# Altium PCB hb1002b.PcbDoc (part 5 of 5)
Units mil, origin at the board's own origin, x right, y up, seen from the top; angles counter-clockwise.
Board outline 2756 x 3549 mil, 2 copper layers (Top Layer, Bottom Layer); 120 components, 136 nets, 498 pads, 328 vias.
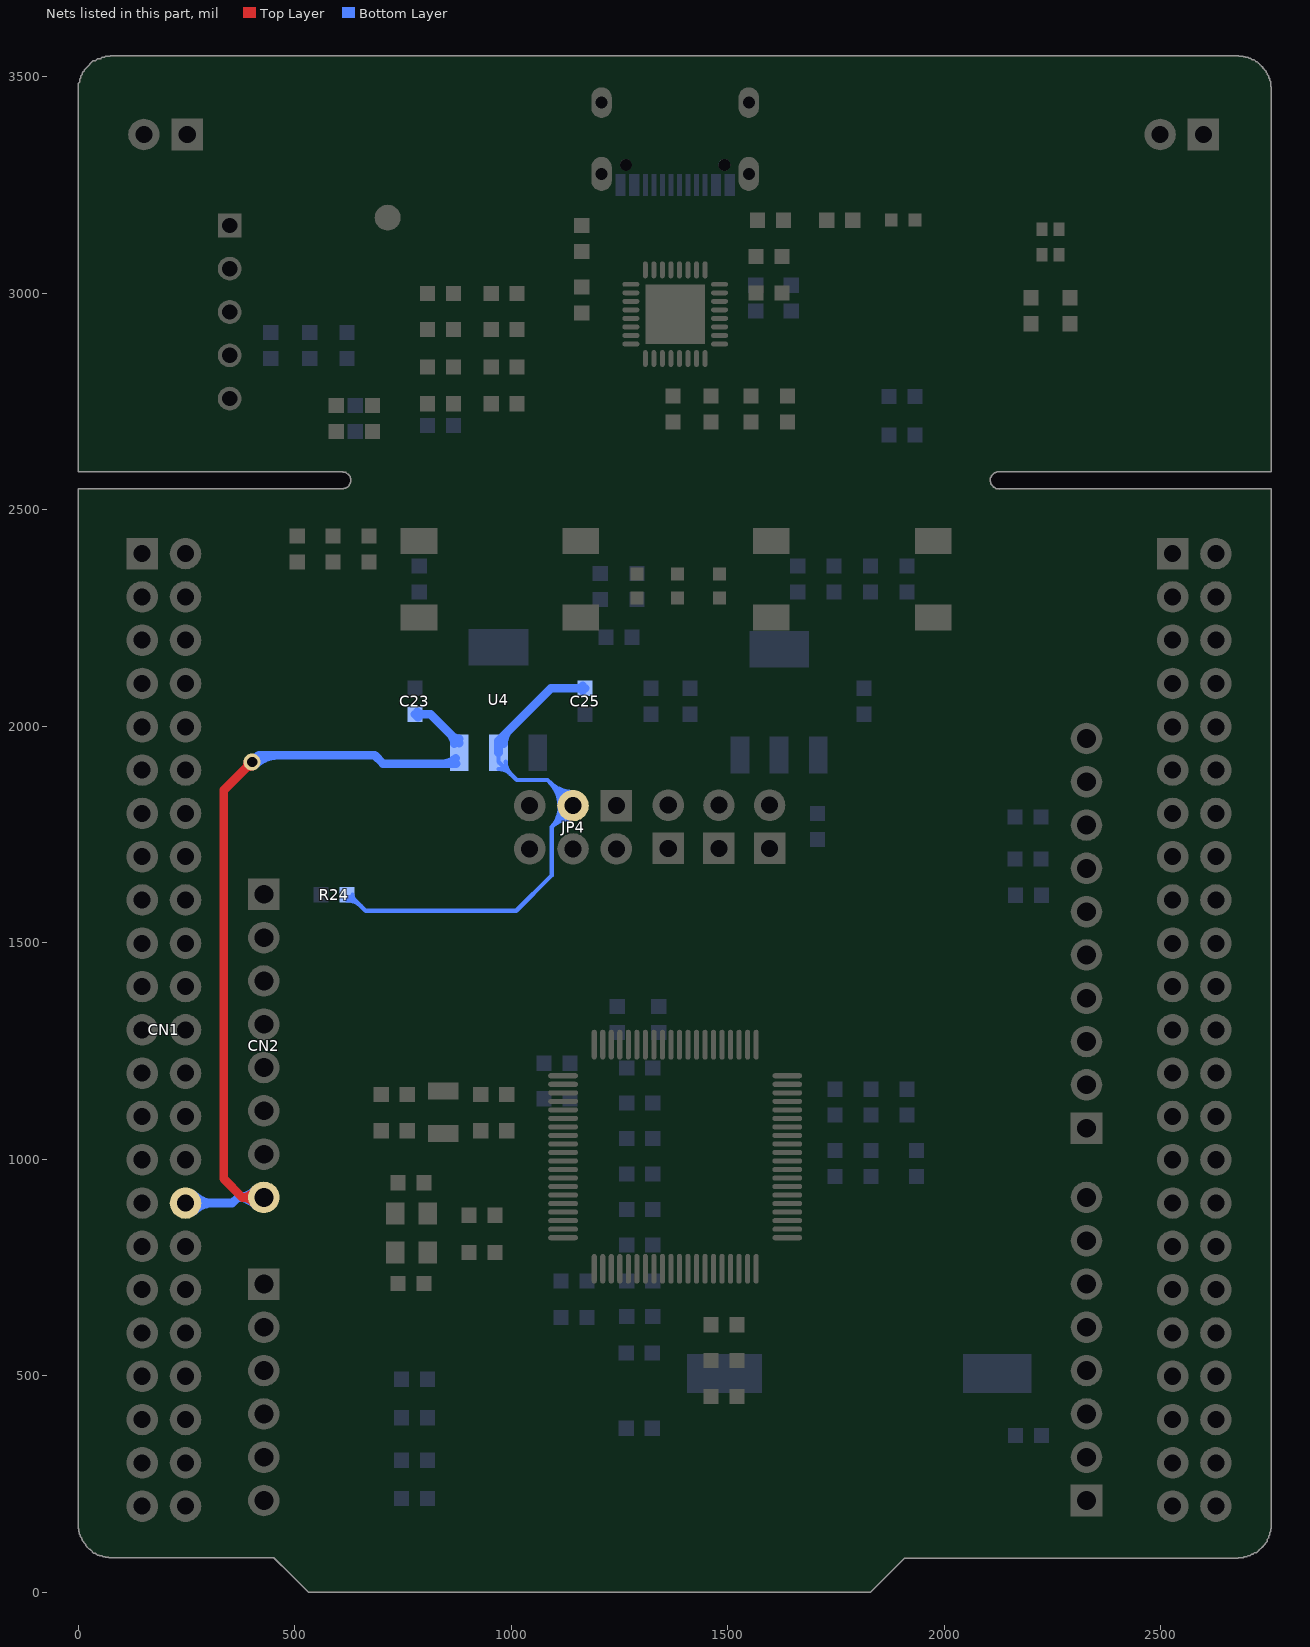
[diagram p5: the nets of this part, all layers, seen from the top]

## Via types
v1: diameter 23.62, hole 11.81, Top Layer to Bottom Layer, tented both sides, 276 vias
v2: diameter 39.37, hole 23.62, Top Layer to Bottom Layer, tented both sides, 27 vias
v3: diameter 15, hole 8, Top Layer to Bottom Layer, tented both sides, 25 vias

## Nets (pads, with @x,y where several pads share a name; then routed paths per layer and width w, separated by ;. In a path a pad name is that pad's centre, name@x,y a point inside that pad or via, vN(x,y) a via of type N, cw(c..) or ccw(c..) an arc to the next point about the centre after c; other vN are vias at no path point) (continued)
VIN: C23.2 CN1.32 CN2.8 U4.3 | length 2454.6
  Top Layer w10: CN2.8@423,900 CN2.8@428,900
  Top Layer w20: 336,982.94 336,999 ; 336,1853 336,999 ; 337,1853 373.5,1889.5 ; 340,1856 373.5,1889.5 ; v2@392.31,1918 cw(c368.93,1918) 385.47,1901.47 cw(c402,1884.93) v2@402,1908.32 ; v2(402,1918) 373.5,1889.5 ; CN2.8@407.18,897.11 ccw(c379,877.89) 379,912 ; CN2.8@407.18,926.89 cw(c379,946.11) 379,912 ; CN2.8@418.47,901.47 419.94,900 CN2.8@423,900 ; CN2.8@429,912 379,912 ; 336,999 336,955 379,912
  Bottom Layer w10: C23.2@778,2021 C23.2@778,2028 ; U4.3@874,1910 U4.3@876,1912
  Bottom Layer w20: CN1.32@248,899 356,899 369,912 ; CN1.32@266.68,880.32 cw(c311.78,835.22) 311.78,899 cw(c311.78,962.78) CN1.32@266.68,917.68 ; v2(402,1918) 417,1933 685,1933 704,1914 U4.3@873,1914 ; v2@408.85,1911.15 cw(c461.59,1858.41) 461.59,1933 ; CN2.8@409.51,894.16 ccw(c369,857.08) 369,912 ; CN2.8@409.51,929.84 cw(c369,966.92) 369,912 ; CN2.8@429,912 369,912 ; C23.2@783.3,2022.7 cw(c796.11,2009.89) 796.11,2028 cw(c796.11,2046.11) C23.2@783.3,2033.3 ; C23.2@785,2021 C23.2@778,2028 814,2028 U4.3@880.45,1961.55 ; 841.98,1914 ccw(c841.98,1956.75) U4.3@872.21,1926.52 ; 859.19,1982.81 cw(c836,1959.62) U4.3@868.8,1959.62 ; U4.3@863.85,1978.15 ccw(c880.45,1994.75) U4.3@880.45,1971.28
VIN_5V: C25.2 JP4.3 R24.1 U4.2 | length 1758.9
  Bottom Layer w10: R24.1@621,1598.5 cw(c621,1553.84) 652.58,1585.42 ; R24.1@625,1605 633,1605 664,1574 1012,1574 1093.58,1655.58 1093.58,1767.58 ; R24.1@633.5,1611 ccw(c649.19,1611) R24.1@638.1,1599.9 ; U4.2@971,1901.63 cw(c971,1862.11) 998.95,1890.05 ; U4.2@971,1918 U4.2@971,1938.95 ; U4.2@973,1916 1013,1876 1084,1876 JP4.3@1143,1817 1093.58,1767.58 ; U4.2@987.65,1918.28 ccw(c1028.54,1918.28) 999.63,1889.37 ; JP4.3@1111.58,1817 ccw(c1035.73,1817) 1089.37,1870.63 ccw(c1143,1924.27) JP4.3@1143,1848.42 ; JP4.3@1111.64,1815.13 cw(c1049.73,1811.44) 1093.58,1767.58 ; JP4.3@1121.62,1815.72 cw(c1079.42,1813.21) 1109.31,1783.31 cw(c1139.21,1753.42) JP4.3@1141.72,1795.62 ; JP4.3@1121.58,1817 ccw(c1069.88,1817) 1106.44,1853.56 ccw(c1143,1890.12) JP4.3@1143,1838.42 ; JP4.3@1141.13,1785.64 ccw(c1137.44,1723.73) 1093.58,1767.58
  Bottom Layer w20: U4.2@971,1938.95 971,1967 1092,2088 C25.2@1171,2088 ; U4.2@982.65,1959.62 cw(c1028.6,1959.62) 996.11,1992.11 ; C25.2@1165.7,2082.7 ccw(c1152.9,2069.9) 1152.9,2088 ccw(c1152.89,2106.11) C25.2@1165.7,2093.3
pads on no net: U2. U2.A5 U2.A8 U2.B5 U2.B8 U3.1 U3.4 U3.8 U3.9 U3.10 U3.16 U3.18 U3.19 U3.27 U3.28 U3.29 U3.30 U4.4 U5.4 Y2.12

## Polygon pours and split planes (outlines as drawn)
GND on Top Layer "Bottom Layer-No Net" (solid, remove dead copper, pour order 1000): 223 vertices, not listed, extent 0,1 2756,3549
GND on Bottom Layer "Bottom Layer-No Net" (solid, remove dead copper, pour order 1001): 284 vertices, not listed, extent 0,1 2756,3549

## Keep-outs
Keep-Out Layer:
  lines w5: -1,2587.98 612,2587.98 ; -0.3,2589.88 0.05,3469.87 -0.3,2590.01 ; 0.05,3469.81 cw(c78.79,3469.81) 78.79,3548.55 2677.22,3548.55 cw(c2677.22,3469.81) 2755.96,3469.81 2755.96,2589 ; 1,2547 0.05,157.99 ccw(c78.79,157.99) 78.79,79.25 447.69,79.25 452.81,79.25 531.55,0.51 1830.76,0.51 ; 612.74,2548.86 ccw(c609.39,2568.85) 616,2588 ; 613.05,2548.61 0.05,2548.61 610.29,2548.61 ; 743,2549 cw(c749.61,2568.15) 746.26,2588.14 ; 746.78,2587.98 1498,2587.98 ; 747,2548.61 1495,2548.61 ; 748,2587.98 1496,2587.98 ; 748.09,2587.98 ccw(c748.09,2568.29) 748.09,2548.61 1496.12,2548.61 ccw(c1496.12,2568.29) 1496.12,2587.98 ; 748.78,2548.61 1500,2548.61 ; 812,2587.98 1425,2587.98 ; 1498.74,2548.86 ccw(c1495.39,2568.85) 1502,2588 ; 1673,2549 cw(c1679.61,2568.15) 1676.26,2588.14 ; 1677,2548.61 1964,2548.61 ; 1679,2587.98 1970,2587.98 ; 1908.32,79.25 2677.22,79.25 ccw(c2677.22,157.99) 2755.96,157.99 2755.96,2548.04 2755.39,2548.61 2126.04,2548.61 cw(c2126.04,2568.29) 2126.04,2587.98 2755.96,2587.98 ; 1909.5,79.25 1830.76,0.51 ; 1968.74,2548.86 ccw(c1965.39,2568.85) 1972,2588 ; 2121,2549 cw(c2127.61,2568.15) 2124.26,2588.14 ; 2125,2548.61 2755,2548.61 ; 2129,2588 2745,2587.98 ; 610.29,2548.61 ccw(c610.29,2568.29) 610.29,2587.98 cw(c610.29,2568.29) 610.29,2548.61 ; 1830.76,0.51 1830.76,0.51 ; 1678.01,2548.61 cw(c1678.01,2568.29) 1678.01,2587.98 1966.59,2587.98 cw(c1966.59,2568.29) 1966.59,2548.61 1678.01,2548.61
Mechanical 1:
  lines w5: -1,2587.98 609.24,2587.98 ; 0.05,2548.61 610.29,2548.61 ; 5.05,2587.98 615.29,2587.98 ; 748.09,2548.61 1496.12,2548.61 ; 750,2587.98 1499,2587.98 ; 753,2587.98 1496,2587.98 ; 1494.88,2548.61 748,2548.61 1497.24,2548.61 ; 1496.12,2587.98 746.78,2587.98 1498,2587.98 ; 1676.01,2548.61 1965.04,2548.61 ; 1680.72,2587.98 1966.59,2587.98 ; 2123,2588 2748.29,2587.98 ; 2124,2548.61 2752.24,2548.61 ; 2126.04,2548.61 2755.96,2548.61 ; 2126.04,2587.98 2755.96,2587.98 ; 2127,2588 2742.24,2587.98 ; 2148.05,2548.61 2754,2549 ; 610.29,2548.61 ccw(c610.29,2568.29) 610.29,2587.98 ; 610.29,2548.61 ccw(c610.29,2568.29) 610.29,2587.98 ; 610.29,2548.61 ccw(c610.29,2568.29) 610.29,2587.98

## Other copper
Top Layer:
  region net VDD_LINK: 2276,3164 2216,3164 2216,3132 2276,3132
Bottom Layer:
  rectangle net VBUS_5V: 1275,3225 1292,3276
  rectangle net VBUS_5V: 1465,3225 1482,3276
  rectangle net GND: 1497,3225 1514,3276
  rectangle net GND: 1245,3225 1262,3276

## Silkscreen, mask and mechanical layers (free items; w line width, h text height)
Top Overlay:
  lines w5: 437,849 448,838 ; 483.31,1355 600,1355 600,1225 ; 484,865 600,865 600,1008 ; 488,162 601,162 ; 488,762 601,762 ; 600,162 600,409 ; 600,535 600,762 ; 876.75,2199.33 1858,2199.33 1858,1879 877,1879 877,2199.33 ; 1329,1643 1641,1643 ; 1637,1643 1681,1643 1681,1771 ; 1682,1771 1994,1771
  text "GND" at 150,3247 h39.37
  text "GND" at 2495,3247 h39.37
  text "LED5" at 2189,3188 h40
  text "VCC" at 99,3136 h40
  text "LED4" at 1845,3072 h40
  text "GND" at 100,3042 h40
  text "SWDIO" at 100,2936 h40
  text "SWCLK" at 99,2836 h40
  text "NRST" at 101,2738 h40
  text "SWD" at 299,2636 h40
  text "LED3" at 1456,2523 h40 r270
  text "LED2" at 1273,2521 h40 r270
  text "LED1" at 1366,2521 h40 r270
  text "RESET" at 897,2479 h40
  text "USER" at 1718,2479 h40
  text "LITE-80" at 466,2242 h40
  text "HB1002B" at 466,2135 h40
  text "SCL/D15" at 2036.22,1953 h40
  text "SDA/D14" at 2055,1856 h35
  text "AREF" at 2145,1753 h35
  text "GND" at 2157.78,1652 h40
  text "E5V" at 1021,1618 h40 r270
  text "VIN5V" at 1117,1618 h40 r270
  text "VBUS" at 1222,1618 h40 r270
  text "BOOT0" at 1340,1618 h40 r270
  text "3V3" at 1457,1618 h40 r270
  text "IDD" at 1577,1618 h40 r270
  text "SCK/D13" at 2027.9,1553 h40
  text "IOREF" at 491,1492 h40
  text "MISO/D12" at 2013.24,1454.5 h40
  text "NRST" at 491,1391 h40
  text "PWM/MOSI/D11" at 1877.46,1353 h40
  text "3V3" at 491,1290 h40
  text "PWM/CS/D10" at 1910.6,1254 h40
  text "5V" at 491,1191 h40
  text "PWM/D9" at 2046.57,1152 h40
  text "GND" at 491,1092 h40
  text "D8" at 2197,1050 h40
  text "POWER" at 650,1035 h40 r90
  text "GND" at 491,993 h40
  text "VIN" at 491,892.09 h40
  text "D7" at 2197.58,891 h40
  text "PWM/D6" at 2045.57,793 h40
  text "PWM/D5" at 2044.66,691 h40
  text "A0" at 491,690 h40
  text "A1" at 491,591 h40
  text "D4" at 2195.68,591 h40
  text "PWM/D3" at 2044.66,494 h40
  text "A2" at 491,492 h40
  text "AIN" at 623,428 h40 r90
  text "A3" at 491,391 h40
  text "D2" at 2197.58,390 h40
  text "TX/D1" at 2118.36,294.72 h40
  text "A4" at 491,292 h40
  text "A5" at 491,192 h40
  text "RX/D0" at 2097.03,192.41 h40
Bottom Overlay:
  lines w5: 1346.9,1724.05 1358.9,1724.05 ; 1627.95,1811.01 1627.95,1823.01 ; 1653.88,1849.05 1665.88,1849.05
  text "PE3" at 378.34,2416 h35 r45
  text "PE2" at 95.67,2415 h35 r45
  text "PE1" at 2749,2410 h35 r45
  text "PE0" at 2469,2405 h35 r45
  text "PE5" at 378.34,2315 h35 r45
  text "PE4" at 96.85,2314 h35 r45
  text "PD15" at 2749,2305 h35 r45
  text "PD14" at 2469,2300 h35 r45
  text "PD6" at 97.08,2214 h35 r45
  text "PD7" at 380.93,2214 h35 r45
  text "PD11" at 2749,2195 h35 r45
  text "PD10" at 2469,2192 h35 r45
  text "PD8" at 98.26,2116 h35 r45
  text "PD9" at 379.75,2115 h35 r45
  text "PD13" at 2749,2103 h35 r45
  text "PD12" at 2469,2100 h35 r45
  text "PC12" at 119,2042 h35 r45
  text "PD2" at 380.93,2016 h35 r45
  text "PC8" at 2749,2012 h35 r45
  text "PC9" at 2469,2006 h35 r45
  text "PC10" at 119,1940 h35 r45
  text "PC11" at 391.07,1927 h35 r45
  text "PC6" at 2749,1910 h35 r45
  text "PB8" at 2469,1905 h35 r45
  text "VMCU" at 119,1837 h35 r45
  text "E_5V" at 402.73,1826 h35 r45
  text "PC7" at 2749,1803 h35 r45
  text "PB9" at 2469,1798 h35 r45
  text "PA13" at 119,1742 h35 r45
  text "GND" at 2749,1711 h35 r45
  text "PA14" at 383.85,1710 h35 r45
  text "PA0" at 2469,1706 h35 r45
  text "GND" at 100.85,1618 h35 r45
  text "PA15" at 382.67,1618 h35 r45
  text "VBUS" at 2749,1609 h35 r45
  text "AGND" at 2469,1593 h35 r45
  text "3V3" at 382.67,1517 h35 r45
  text "PD1" at 87.66,1508 h35 r45
  text "PC0" at 2749,1506 h35 r45
  text "PA5" at 2469,1501 h35 r45
  text "NRST" at 385.26,1417 h35 r45
  text "PD0" at 98.26,1415 h35 r45
  text "PC1" at 2749,1406 h35 r45
  text "PA6" at 2469,1401 h35 r45
  text "3V3" at 382.67,1316 h35 r45
  text "PD3" at 98.26,1315 h35 r45
  text "PC3" at 2749,1308 h35 r45
  text "PA7" at 2469,1303 h35 r45
  text "5V" at 382.67,1218 h35 r45
  text "PD4" at 99.44,1214 h35 r45
  text "PC4" at 2749,1206 h35 r45
  text "PB0" at 2469,1201 h35 r45
  text "GND" at 383.53,1119 h35 r45
  text "GND" at 100.85,1118 h35 r45
  text "GND" at 2749,1110 h35 r45
  text "PB1" at 2469,1105 h35 r45
  text "GND" at 383.53,1013 h35 r45
  text "PB7" at 98.26,1012 h35 r45
  text "PB6" at 2749,1005 h35 r45
  text "PA9" at 2469,1000 h35 r45
  text "PC13" at 119,938 h35 r45
  text "VIN" at 383.53,909 h35 r45
  text "PB2" at 2749,908 h35 r45
  text "PA8" at 2469,904 h35 r45
  text "PC15" at 119,842 h35 r45
  text "PD5" at 380.93,816 h35 r45
  text "PB15" at 2749,804 h35 r45
  text "PB14" at 2469,799 h35 r45
  text "PC14" at 119,744 h35 r45
  text "PA1" at 372.92,713 h35 r45
  text "PB13" at 2749,704 h35 r45
  text "PB5" at 2469,699 h35 r45
  text "PA2" at 383.53,618 h35 r45
  text "PF1" at 83.77,607 h35 r45
  text "PB12" at 2749,603 h35 r45
  text "PB4" at 2469,598 h35 r45
  text "PA3" at 383.53,515 h35 r45
  text "PF0" at 94.37,514 h35 r45
  text "AGND" at 2749,509 h35 r45
  text "PB3" at 2469,504 h35 r45
  text "VBAT" at 119,438 h35 r45
  text "PA4" at 384.7,417 h35 r45
  text "PA10" at 2469,409 h35 r45
  text "PA0" at 2749,409 h35 r45
  text "PB10" at 383.53,319 h35 r45
  text "PC2" at 100.85,318 h35 r45
  text "PA11" at 2469,310 h35 r45
  text "VLCD" at 2749,310 h35 r45
  text "PB11" at 383.53,217 h35 r45
  text "PC5" at 100.85,216 h35 r45
  text "GND" at 2749,210 h35 r45
  text "PA12" at 2469,204 h35 r45
Mechanical 1:
  lines w5: 0.05,159.99 1,2549 ; 0.05,2244.67 0.05,158.05 ccw(c78.79,158.05) 78.79,79.31 447.69,79.32 452.81,79.32 531.55,0.57 1830.76,0.57 ; 0.05,3469.87 cw(c78.79,3469.87) 78.79,3548.61 2677.22,3548.61 cw(c2677.22,3469.87) 2755.96,3469.87 ; 12.29,2548.61 610.29,2548.61 ; 1494.77,2549.12 ccw(c1494.88,2569.12) 1501.15,2588.12 ; 1501.24,2587.6 1501.32,2587.58 ; 1908.32,79.31 2677.22,79.31 ccw(c2677.22,158.05) 2755.96,158.05 2755.96,2546 ; 1909.5,79.32 1830.76,0.57 ; 1964.93,2548.59 ccw(c1965.04,2569.09) 1971.46,2588.56 ; 1971.52,2588.55 1971.53,2588.55 ; 2755.96,2589 2755.96,3469.81 ; 1830.76,0.57 1830.76,0.57 ; -0.3,2590.01 0.05,3470 -0.3,2590.01

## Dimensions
78.79,3548.55 to 531.55,0.51 on Drill Drawing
